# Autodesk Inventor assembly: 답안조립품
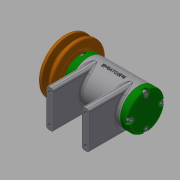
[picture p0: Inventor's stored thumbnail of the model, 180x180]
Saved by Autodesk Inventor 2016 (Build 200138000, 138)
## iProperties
Created: 2020-07
Part Number: 답안조립품
Material: 일반
Document SubType Name: Assembly
Designer: 605-12
Author: 605-12
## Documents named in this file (15)
- C:\Users\605-12\Desktop\700706V1007\답안조립품.iam
- C:\Users\605-12\Desktop\700706V1007\본체.ipt
- C:\Users\605-12\Desktop\700706V1007\베어링 6002.ipt
- C:\Users\605-12\Desktop\700706V1007\축.ipt
- C:\Users\605-12\Desktop\700706V1007\뒤커버.ipt
- C:\Users\605-12\Desktop\700706V1007\앞커버.ipt
- C:\Users\605-12\Desktop\700706V1007\볼트 M4x12.ipt
- C:\Users\605-12\Desktop\700706V1007\오일 실 15 25 7.ipt
- C:\Users\605-12\Desktop\700706V1007\키 3x3x12.ipt
- C:\Users\605-12\Desktop\700706V1007\V벨트풀리.ipt
- C:\Users\605-12\Desktop\700706V1007\와셔 8x17.ipt
- C:\Users\605-12\Desktop\700706V1007\스프링와셔 8.ipt
- C:\Users\605-12\Desktop\700706V1007\너트 M8.ipt
- C:\Users\605-12\Desktop\700706V1007\볼트 M6x8.ipt
- C:\Users\605-12\Desktop\700706V1007\와셔 6x11.5.ipt
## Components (1 placed, 1 different names)
1. V벨트풀리:1
